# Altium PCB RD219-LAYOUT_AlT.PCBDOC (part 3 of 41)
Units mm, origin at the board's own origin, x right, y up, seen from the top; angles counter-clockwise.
Board outline 209.75 x 159.97 mm, 2 copper layers (TOP, BOTTOM), stack 0 mm thick; 398 components, 199 nets, 1469 pads, 0 vias.
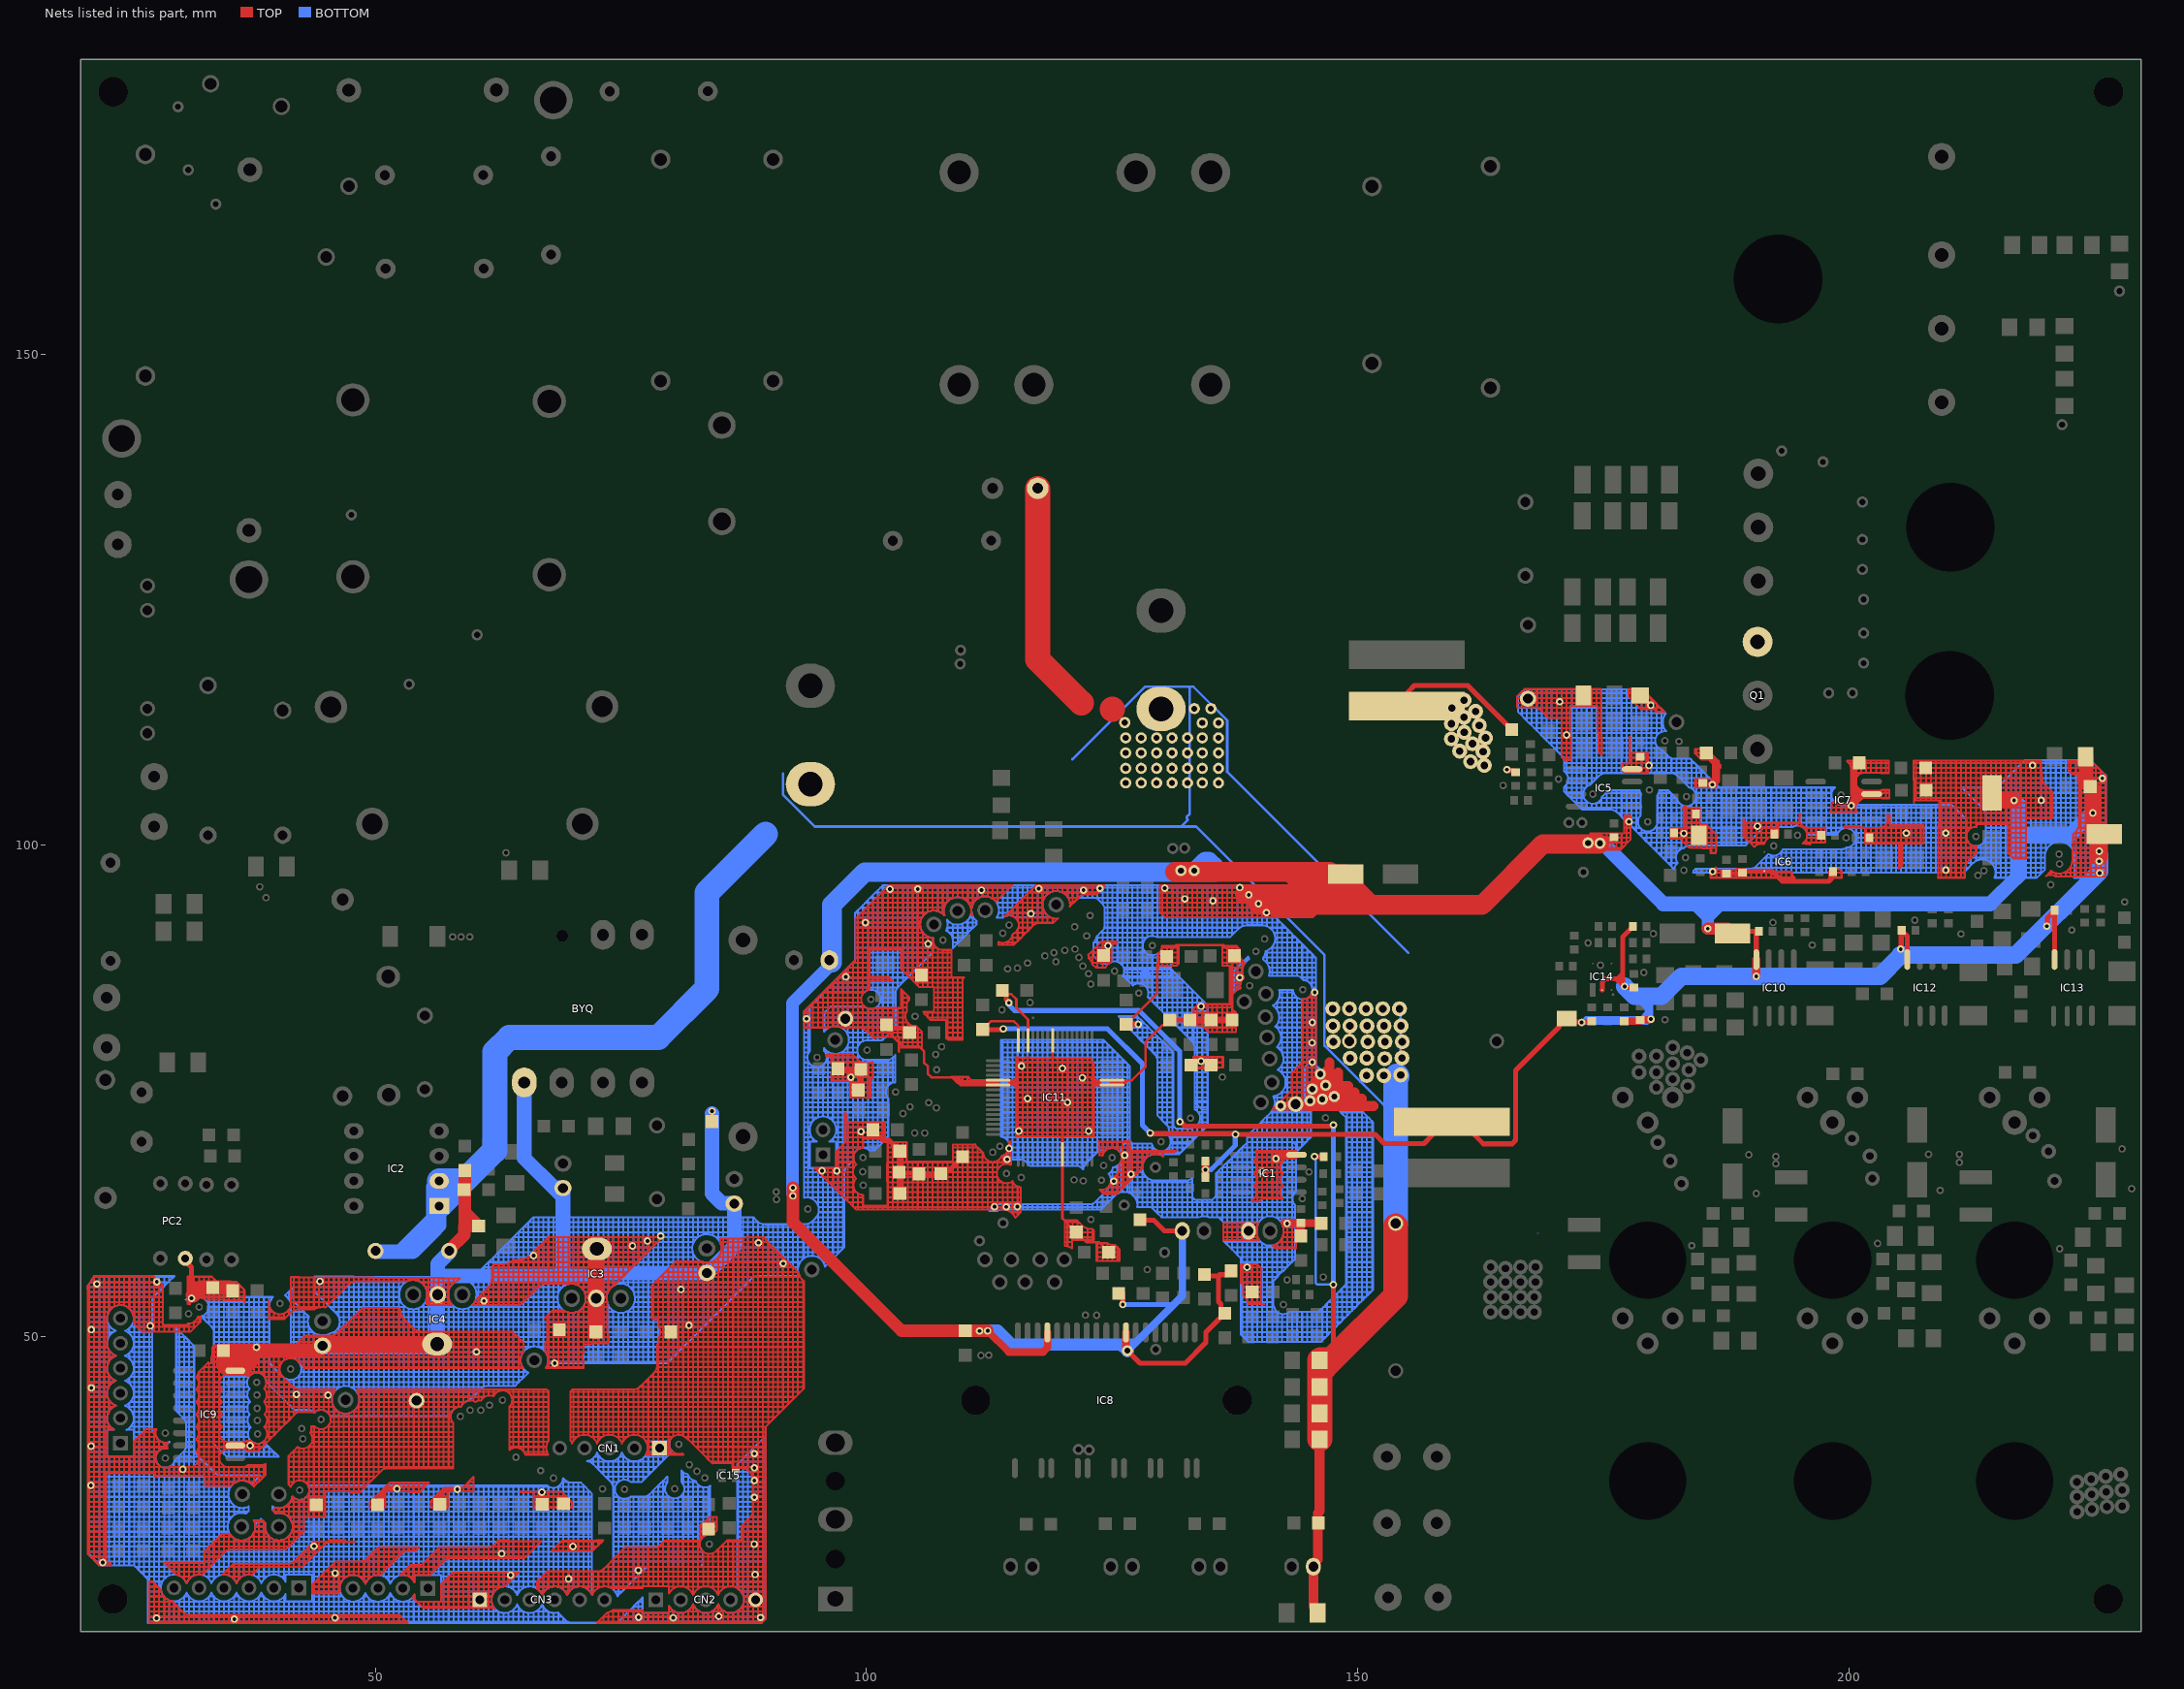
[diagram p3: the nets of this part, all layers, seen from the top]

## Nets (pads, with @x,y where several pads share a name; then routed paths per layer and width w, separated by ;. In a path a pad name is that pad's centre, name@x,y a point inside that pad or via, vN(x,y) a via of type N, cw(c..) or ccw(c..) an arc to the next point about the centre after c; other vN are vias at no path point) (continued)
GND: (continued)
  TOP w0.203: 21.355,56.068 21.397,56.068 ; 21.397,56.132 21.397,56.068 ; 21.905,56.194 21.905,56.068 ; 22.607,34.572 cw(c23.429,34.808) 22.577,34.732 ; 22.609,34.563 22.609,34.224 ; 22.611,35.058 ccw(c23.429,34.808) 22.609,35.053 ; 22.713,44.304 cw(c24.064,44.257) 22.714,44.315 ; 22.712,49.34 22.712,49.464 ; 22.712,51.874 22.712,51.496 ; 22.765,41.344 ccw(c24.064,41.717) 22.767,41.336 ; 22.765,46.424 ccw(c24.064,46.797) 22.767,46.416 ; 22.769,43.869 cw(c23.429,44.177) 22.765,43.876 ; 22.771,41.322 cw(c24.064,41.717) 22.767,41.336 ; 22.771,43.862 ccw(c24.064,44.257) 22.918,43.541 ccw(c24.064,44.257) 22.921,43.536 ; 22.771,46.402 cw(c24.064,46.797) 22.767,46.416 ; 22.921,52.598 22.921,53.02 ; 23.409,40.535 cw(c24.064,41.717) 23.046,40.828 ; 23.42,40.529 22.921,40.529 ; 25.098,36.111 24.953,36.111 ; 25.112,36.111 25.461,36.111 ; 25.416,51.874 25.416,51.496 ; 25.461,56.171 25.461,56.068 ; 26.477,56.164 26.477,56.068 ; 27.46,56.157 26.985,56.16 ; 27.661,37.773 ccw(c28.636,37.653) 27.73,37.272 ; 27.662,37.78 27.493,37.78 ; 27.663,37.79 cw(c28.636,37.653) 27.886,38.288 ; 28.192,24.22 28.001,24.411 ; 28.194,24.21 ccw(c29.525,24.445) 28.228,24.064 ; 28.4,53.673 28.4,53.528 ; 28.4,53.687 28.4,54.036 ; 28.505,23.558 ccw(c29.525,24.445) 28.507,23.556 ; 28.521,23.541 cw(c29.525,24.445) 28.509,23.554 ; 28.525,27.003 29.017,27.003 ; 28.527,27.001 29.017,26.511 ; 28.856,38.609 cw(c29.72,38.923) 28.855,38.611 ; 28.856,39.237 ccw(c29.72,38.923) 28.855,39.235 ; 28.857,38.61 ccw(c28.636,37.653) 28.855,38.611 ; 28.857,39.236 cw(c28.636,40.193) 28.855,39.235 ; 28.924,26.604 29.017,26.604 ; 29.127,36.802 cw(c28.636,37.653) 29.126,36.801 ; 29.29,23.114 cw(c29.525,24.445) 29.019,23.192 cw(c29.525,24.445) 29.017,23.193 ; 29.3,23.112 29.364,23.048 ; 29.374,36.801 29.126,36.801 ; 29.375,36.801 ccw(c29.72,37.653) 29.486,36.764 ; 29.736,25.78 cw(c29.525,24.445) 29.75,25.778 ; 30.128,27.003 30.033,27.003 ; 30.142,27.003 30.541,27.003 ; 30.178,35.857 30.033,35.857 ; 30.192,35.857 30.541,35.857 ; 30.241,25.591 ccw(c29.525,24.445) 30.033,25.698 ; 30.246,25.588 30.541,25.588 ; 30.261,25.579 cw(c29.525,24.445) 30.541,25.336 ; 30.396,22.016 30.38,22.032 ; 30.898,51.353 ccw(c31.001,52.33) 30.904,51.353 ; 30.898,53.308 cw(c31.001,52.33) 30.904,53.308 ; 30.904,53.673 30.904,53.528 ; 30.904,53.687 30.904,54.036 ; 31.045,25.332 ccw(c32.065,24.445) 30.872,25.08 ; 31.049,25.336 31.049,25.588 ; 31.049,56.133 31.049,56.068 ; 31.061,25.349 cw(c32.065,24.445) 31.344,25.588 ; 31.121,53.306 ccw(c31.001,52.33) 31.049,53.312 ; 31.127,53.296 cw(c32.071,53.026) 31.227,53.528 ; 31.778,38.285 ccw(c31.117,38.923) 31.781,38.288 ; 31.778,38.291 cw(c31.117,37.653) 31.781,38.288 ; 31.778,39.555 ccw(c31.117,40.193) 31.781,39.558 ; 31.778,39.561 cw(c31.117,38.923) 31.781,39.558 ; 31.778,40.825 ccw(c31.117,41.463) 31.781,40.828 ; 31.778,40.831 cw(c31.117,40.193) 31.781,40.828 ; 31.778,42.095 ccw(c31.117,42.733) 31.949,42.345 ; 31.778,43.365 ccw(c31.117,44.003) 31.781,43.368 ; 31.778,43.371 cw(c31.117,42.733) 31.781,43.368 ; 31.778,44.635 ccw(c31.117,45.273) 31.781,44.638 ; 31.778,44.641 cw(c31.117,44.003) 31.781,44.638 ; 31.778,45.905 ccw(c31.117,46.543) 31.781,45.908 ; 31.778,45.911 cw(c31.117,45.273) 31.781,45.908 ; 31.789,42.09 cw(c31.117,41.463) 31.953,41.844 ; 31.941,52.043 cw(c31.001,52.33) 31.928,52.004 ; 31.95,39.805 cw(c31.117,40.193) 31.781,39.558 ; 31.95,44.885 cw(c31.117,45.273) 31.781,44.638 ; 31.951,52.05 ccw(c32.071,53.026) 32.065,52.043 ; 31.953,39.812 32.065,39.812 ; 31.953,42.352 32.065,42.352 ; 31.953,44.892 32.065,44.892 ; 31.956,39.819 ccw(c31.117,40.193) 32.036,40.193 ccw(c31.117,40.193) 32.027,40.32 ; 31.956,42.359 ccw(c31.117,42.733) 32.036,42.733 ccw(c31.117,42.733) 32.027,42.86 ; 31.956,44.899 ccw(c31.117,45.273) 32.036,45.273 ccw(c31.117,45.273) 32.027,45.4 ; 32.024,46.399 cw(c31.117,46.543) 31.781,45.908 ; 32.025,46.405 32.036,46.416 ; 32.065,56.127 32.065,56.068 ; 32.1,51.42 32.065,51.386 ; 32.21,51.52 32.21,52.004 ; 32.225,52.055 cw(c32.071,53.026) 32.21,52.053 ; 32.346,25.767 ccw(c32.065,24.445) 32.065,25.797 ; 32.355,25.765 32.573,25.983 ; 32.631,28.183 32.631,28.128 ; 32.716,53.767 ccw(c32.071,53.026) 32.573,53.87 ; 32.72,53.764 33.081,53.764 ; 33.02,47.4 32.943,47.323 ; 33.081,28.622 33.081,28.128 ; 33.317,47.846 33.317,47.432 ; 33.589,49.087 33.589,48.956 ; 34.21,37.279 ccw(c35.05,37.653) 34.213,37.272 ; 34.21,41.837 ccw(c35.05,41.463) 34.139,41.336 ; 34.21,44.377 ccw(c35.05,44.003) 34.139,43.876 ; 34.213,41.844 34.097,41.844 ; 34.213,44.384 34.097,44.384 ; 34.217,37.265 cw(c35.05,37.653) 34.213,37.272 ; 34.217,41.851 cw(c35.05,41.463) 34.388,42.101 ; 34.217,44.391 cw(c35.05,44.003) 34.388,44.641 ; 34.377,42.106 cw(c35.05,42.733) 34.213,42.352 ; 34.377,44.646 cw(c35.05,45.273) 34.213,44.892 ; 34.388,40.825 cw(c35.05,41.463) 34.385,40.828 ; 34.388,40.831 ccw(c35.05,40.193) 34.385,40.828 ; 34.388,43.365 cw(c35.05,44.003) 34.385,43.368 ; 34.388,43.371 ccw(c35.05,42.733) 34.385,43.368 ; 34.436,25.786 34.605,25.955 ; 34.44,25.787 cw(c34.605,24.445) 34.605,25.797 ; 34.604,36.849 cw(c35.05,37.653) 34.213,37.272 ; 34.604,38.457 ccw(c35.05,37.653) 34.385,38.288 ; 34.604,39.389 cw(c35.05,40.193) 34.213,39.812 ; 34.714,53.727 35.113,53.727 ; 34.714,53.764 34.605,53.764 ; 34.718,28.128 34.605,28.128 ; 35.182,29.946 ccw(c36.383,30.668) 35.186,29.939 ; 35.353,34.826 35.113,34.826 ; 35.359,34.833 cw(c36.463,33.97) 35.62,35.089 cw(c36.463,33.97) 35.621,35.09 ; 35.871,35.24 cw(c36.463,33.97) 36.124,35.33 cw(c36.463,33.97) 36.129,35.331 ; 36.116,29.292 cw(c36.383,30.668) 35.621,29.492 ; 36.125,25.332 ccw(c37.145,24.445) 35.952,25.08 ; 36.129,25.336 36.129,25.588 ; 36.129,29.29 36.129,29.144 ; 36.14,29.288 ccw(c36.383,30.668) 36.637,29.29 ; 36.141,25.349 cw(c37.145,24.445) 36.424,25.588 ; 36.626,29.288 ccw(c36.383,30.668) 36.637,29.29 ; 36.65,29.292 cw(c36.383,30.668) 36.637,29.29 ; 36.704,53.727 36.637,53.727 ; 36.732,53.419 36.732,54.036 ; 36.947,39.422 cw(c36.447,40.193) 36.68,39.304 ; 36.947,46.044 ccw(c36.447,45.273) 36.946,46.045 ; 36.948,39.423 37.145,39.423 ; 37.012,36.929 cw(c36.447,37.653) 37.007,36.924 ; 37.012,38.377 ccw(c36.447,37.653) 37.007,38.382 ; 37.126,29.479 cw(c36.383,30.668) 36.637,29.29 ; 37.145,29.492 37.145,29.144 ; 37.146,29.493 ccw(c36.383,30.668) 37.349,29.652 ; 37.223,46.042 cw(c37.93,45.359) 37.226,46.045 ; 37.317,39.427 ccw(c38.024,40.11) 37.321,39.423 ; 37.426,25.767 ccw(c37.145,24.445) 37.145,25.797 ; 37.435,25.765 37.653,25.983 ; 37.615,31.336 38.161,31.336 ; 37.621,31.326 cw(c36.383,30.668) 37.689,31.176 ; 37.639,34.732 38.669,35.762 ; 37.638,34.733 ccw(c36.463,33.97) 37.145,35.194 ; 37.653,30.076 ccw(c36.383,30.668) 37.689,30.16 ; 37.653,34.746 37.653,35.24 ; 38.147,35.24 37.653,35.24 ; 38.161,35.254 38.161,35.748 ; 38.655,35.748 38.161,35.748 ; 38.668,39.368 cw(c38.024,40.11) 38.586,39.304 ; 38.674,43.393 ccw(c37.967,44.076) 38.929,43.876 ; 38.68,43.395 cw(c37.973,42.712) 38.705,43.368 ; 38.694,44.741 ccw(c37.93,45.359) 38.795,44.892 ; 38.697,44.733 cw(c37.967,44.076) 38.9,44.384 ; 38.706,40.817 cw(c38.024,40.11) 38.983,40.32 ; 38.714,40.814 ccw(c37.995,41.485) 38.726,40.828 ; 38.747,42.107 ccw(c37.973,42.712) 38.887,42.352 ; 38.759,42.103 cw(c37.995,41.485) 38.91,41.844 ; 38.829,37.058 38.829,36.764 ; 38.833,31.007 ccw(c40.193,30.668) 38.831,30.999 ; 39.168,29.712 cw(c40.193,30.668) 38.887,30.16 ; 39.177,29.702 39.177,29.652 ; 39.185,29.694 ccw(c40.193,30.668) 39.227,29.652 ; 39.195,53.386 ccw(c40.296,53.386) 39.207,53.224 ; 39.195,53.419 39.195,53.727 ; 39.685,32.432 39.685,32.206 ; 39.854,32.028 cw(c40.193,30.668) 39.862,32.03 ; 39.854,32.61 ccw(c40.193,33.97) 39.862,32.608 ; 40.181,52.291 cw(c40.296,53.386) 39.685,52.47 ; 40.193,52.29 40.193,52.004 ; 40.2,52.289 ccw(c40.296,53.386) 40.701,52.362 ; 40.624,45.908 40.193,45.908 ; 40.695,31.977 ccw(c40.193,30.668) 40.193,32.07 ; 40.701,31.974 40.701,32.192 ; 40.701,45.831 40.701,45.4 ; 40.718,31.968 cw(c40.193,30.668) 41.159,31.684 ; 40.785,32.7 cw(c40.193,33.97) 40.701,32.664 ; 41.176,34.969 41.176,35.24 ; 41.184,34.961 cw(c40.193,33.97) 41.209,34.936 ; 41.209,37.893 41.209,37.78 ; 41.355,52.411 41.209,52.264 ; 41.378,34.709 cw(c42.307,34.389) 41.38,34.715 ; 41.382,34.713 ccw(c40.193,33.97) 41.38,34.715 ; 41.573,33.727 cw(c40.193,33.97) 41.369,33.208 ; 41.574,44.959 41.209,45.323 ; 41.577,33.732 ccw(c42.307,34.389) 41.717,33.604 ; 41.716,35.174 ccw(c42.307,34.389) 41.38,34.715 ; 42.09,38.785 ccw(c42.625,39.609) 42.097,38.781 ; 42.211,29.652 41.717,29.652 ; 42.225,27.606 42.225,27.112 ; 42.278,49.511 42.739,49.972 ; 42.592,26.604 42.225,26.604 ; 42.719,30.16 42.225,30.16 ; 42.733,26.745 42.733,27.112 ; 42.733,28.114 42.733,27.62 ; 42.733,49.966 42.733,49.464 ; 43.1,27.112 42.733,27.112 ; 43.241,27.253 43.241,27.62 ; 43.241,28.622 43.241,28.128 ; 43.389,40.227 cw(c42.625,39.609) 43.587,39.812 ; 43.396,40.227 ccw(c42.513,40.658) 43.435,40.32 ; 43.466,40.896 cw(c42.513,40.658) 43.467,40.891 ; 43.608,27.62 43.241,27.62 ; 43.749,27.761 43.749,28.128 ; 43.749,29.13 pad.@43.749,28.636 ; 43.788,40.895 ccw(c44.482,41.59) 43.792,40.891 ; 43.84,52.806 cw(c44.575,51.583) 43.842,52.808 ; 43.857,42.348 43.749,42.348 ; 43.862,42.352 43.749,42.352 ; 43.864,42.354 cw(c44.482,41.59) 44.257,42.546 ; 44.116,28.128 43.749,28.128 ; 44.245,40.637 cw(c44.482,41.59) 43.862,40.828 ; 44.257,28.269 44.257,28.636 ; 44.257,40.634 44.257,40.32 ; 44.261,40.633 ccw(c44.482,41.59) 44.765,40.649 ; 44.624,28.636 44.257,28.636 ; 44.91,31.779 44.91,31.684 ; 44.91,31.793 44.91,32.192 ; 44.949,52.988 ccw(c44.702,51.583) 44.765,53.009 ; 44.956,52.987 45.273,53.304 ; 44.989,53.02 44.765,53.02 ; 45.101,42.354 ccw(c44.482,41.59) 44.77,42.53 ccw(c44.482,41.59) 44.765,42.531 ; 45.103,42.352 45.273,42.352 ; 45.114,42.343 cw(c44.482,41.59) 45.273,42.173 ; 45.267,40.999 cw(c44.482,41.59) 45.103,40.828 ; 45.273,41.007 45.273,40.828 ; 45.277,41.012 ccw(c44.482,41.59) 45.432,41.336 ; 45.497,53.528 45.273,53.528 ; 45.954,44.532 ccw(c46.979,43.576) 45.949,44.527 ; 46.278,42.363 cw(c46.979,43.576) 45.781,42.849 ; 46.289,42.357 46.289,42.352 ; 46.293,50.501 46.78,50.988 ; 46.297,42.352 46.289,42.352 ; 46.3,42.351 ccw(c46.979,43.576) 46.797,42.187 ; 46.79,25.369 ccw(c47.729,24.397) 46.562,25.08 ; 46.797,25.376 46.797,25.588 ; 46.797,51.005 46.797,50.988 ; 46.807,25.386 cw(c47.729,24.397) 47.09,25.588 ; 47.214,55.245 47.021,55.052 ; 47.8,25.747 cw(c47.729,24.397) 47.813,25.746 ; 47.823,25.745 ccw(c47.729,24.397) 47.813,25.746 ; 47.892,29.111 46.797,29.111 ; 47.926,29.144 46.797,29.144 ; 47.944,29.162 46.942,29.162 46.942,29.289 46.797,29.289 ; 48.153,44.343 48.153,44.384 ; 48.155,44.34 cw(c46.979,43.576) 48.321,43.981 ; 48.18,42.855 ccw(c46.979,43.576) 48.184,42.86 ; 48.193,42.876 cw(c46.979,43.576) 48.184,42.86 ; 48.363,25.59 ccw(c47.729,24.397) 48.321,25.612 ; 48.368,25.588 48.829,25.588 ; 48.384,25.579 cw(c47.729,24.397) 48.829,25.182 ; 49.33,25.369 ccw(c50.269,24.397) 49.102,25.08 ; 49.337,25.376 49.337,25.588 ; 49.337,27.606 49.337,27.112 ; 49.347,25.386 cw(c50.269,24.397) 49.63,25.588 ; R74.1@49.845,33.524 R74.1@49.845,33.208 ; 50.353,34.032 50.353,33.716 ; 50.48,25.732 ccw(c50.269,24.397) 50.353,25.746 ; 50.482,25.732 50.847,26.096 ; 50.516,36.256 50.353,36.256 ; 52.531,25.72 52.893,26.082 ; 52.551,25.724 cw(c52.809,24.397) 52.893,25.746 ; 52.936,51.799 53.239,51.496 ; 53.248,55.642 52.893,55.642 ; 53.259,55.647 cw(c53.862,54.354) 53.401,55.704 ; 53.51,34.206 53.909,34.206 ; 53.51,34.224 53.909,34.224 ; 53.51,34.282 53.401,34.282 ; 53.813,50.922 53.747,50.988 ; 53.813,23.493 ccw(c52.809,24.397) 53.867,23.556 ; 53.815,23.465 53.997,23.283 ; 53.909,23.371 53.909,23.556 ; 53.991,23.742 cw(c52.809,24.397) 53.909,23.612 ; 53.997,23.753 53.997,23.556 ; 54.002,25.032 ccw(c52.809,24.397) 53.997,25.041 ; 54.417,22.863 54.417,23.045 ; 55.241,53.857 ccw(c53.862,54.227) 55.243,53.865 ; 57.835,53.235 cw(c58.862,54.227) 57.618,53.528 ; 57.842,53.229 57.465,53.229 ; 57.925,36.604 57.465,36.604 ; 57.926,41.238 cw(c58.656,41.895) 57.848,41.336 ; 57.928,36.606 57.928,36.764 ; 57.928,41.236 57.928,40.828 ; 57.964,55.463 ccw(c58.862,54.354) 57.618,55.052 ; 57.973,55.47 57.973,55.56 ; 57.974,42.602 cw(c58.656,41.895) 58.471,42.86 ; 57.983,55.478 cw(c58.862,54.354) 58.1,55.56 ; 58.351,55.686 ccw(c58.862,54.354) 58.344,55.683 ; 58.723,42.866 cw(c59.646,42.53) 58.989,43.261 ; 58.725,42.875 ccw(c58.656,41.895) 58.486,42.863 ccw(c58.656,41.895) 58.481,42.862 ; 59.87,34.216 60.005,34.216 ; 59.87,34.224 60.005,34.224 ; 59.87,34.276 59.497,34.276 ; 59.882,53.229 60.005,53.229 ; 59.889,53.235 ccw(c58.862,54.227) 60.005,53.372 ; 59.998,43.447 ccw(c59.646,42.53) 59.497,43.501 ; 60.005,43.445 60.005,43.876 ; 60.014,43.441 cw(c59.646,42.53) 60.195,43.345 ; 60.194,53.715 cw(c58.862,54.227) 60.192,53.708 ; 60.206,43.354 cw(c60.741,42.53) 60.513,43.486 ; 60.513,54.03 60.513,53.528 ; 60.772,43.514 cw(c61.632,43.038) 61.021,43.808 ; 60.776,43.512 ccw(c60.741,42.53) 60.52,43.487 ccw(c60.741,42.53) 60.513,43.486 ; 61.021,54.538 61.021,54.036 ; 61.468,54.984 61.027,54.544 ; 62.037,57.332 62.037,57.084 ; 62.047,43.929 ccw(c61.632,43.038) 62.042,43.931 ; 62.16,22.354 cw(c63.18,23.241) 62.145,22.372 ; 63.18,24.593 ccw(c63.18,23.241) 63.053,24.587 ; 63.186,24.593 63.561,24.967 ; 63.61,29.212 64.069,29.212 ; 63.61,29.283 63.561,29.283 ; 63.672,38.481 cw(c64.317,37.739) 63.675,38.483 ; 63.675,42.887 63.675,42.86 ; 63.676,42.889 ccw(c62.946,43.546) 63.913,43.368 ; 64.017,57.787 64.069,57.787 ; 64.731,34.211 pad.@66.609,34.211 ; 64.738,34.204 66.113,34.204 66.113,33.716 ; 64.941,49.525 64.577,49.889 ; 64.941,53.391 64.779,53.229 64.577,53.229 ; 64.943,53.392 65.079,53.528 ; 64.983,49.464 64.577,49.464 ; 65.028,46.827 cw(c66.19,47.61) 65.02,46.838 ; 65.091,48.48 65.091,48.956 ; 65.091,49.396 65.091,48.956 ; 65.262,38.01 ccw(c64.317,37.739) 65.132,38.288 ; 65.263,38.004 65.593,38.004 ; 65.325,27.62 65.085,27.62 ; 65.583,58.118 cw(c64.827,59.239) 65.555,58.1 ; 65.738,29.213 66.609,29.213 ; pad.@65.783,58.283 cw(c64.827,59.239) 65.602,58.132 ; pad.@65.784,58.284 cw(c64.827,59.239) 65.602,58.132 ; pad.@65.799,58.3 cw(c64.827,59.239) 65.784,58.285 pad.@66.107,58.608 ; pad.@66.101,58.602 pad.@66.101,58.1 ; 66.113,29.212 66.101,29.212 ; 66.341,28.636 66.101,28.636 ; 66.436,24.387 cw(c65.72,23.241) 66.449,24.379 ; 66.475,28.77 66.101,28.396 ; 66.475,28.771 66.609,28.904 ; 66.541,54.991 66.101,54.55 ; 66.609,59.11 66.609,58.608 ; 66.785,24.073 ccw(c65.72,23.241) 66.609,24.259 ; 66.792,24.064 67.117,24.064 ; 66.799,24.054 cw(c65.72,23.241) 66.99,23.704 cw(c68.26,23.241) 67.114,23.957 cw(c68.26,23.241) 67.117,23.962 ; 67.117,59.618 67.117,59.116 ; 67.249,51.876 67.323,51.95 ; 67.294,48.474 67.294,48.956 ; 67.294,48.473 cw(c66.19,47.61) 67.314,48.448 ; 67.36,46.838 67.625,46.838 ; 67.365,46.847 ccw(c66.19,47.61) 67.412,46.924 ; 67.469,38.296 ccw(c68.768,38.669) 67.471,38.288 ; 67.475,38.274 cw(c68.768,38.669) 67.471,38.288 ; 67.586,38.014 cw(c68.768,38.669) 67.471,38.288 ; 67.591,38.004 67.117,38.004 ; 67.625,60.126 67.625,59.624 ; 67.661,39.444 ccw(c68.768,38.669) 67.625,39.39 ; 67.666,39.452 67.666,39.812 ; 68.133,28.368 68.133,28.222 ; 69.152,52.691 ccw(c69.991,53.846) 69.161,52.684 ; 69.325,24.073 ccw(c68.26,23.241) 69.149,24.259 ; 69.332,24.064 69.657,24.064 ; 69.339,24.054 cw(c68.26,23.241) 69.53,23.704 cw(c70.8,23.241) 69.654,23.957 cw(c70.8,23.241) 69.657,23.962 ; 69.792,55.386 cw(c69.991,53.973) 69.806,55.388 ; 69.87,39.452 69.87,39.812 ; 69.875,39.444 cw(c68.768,38.669) 69.961,39.304 ; 70.016,29.241 70.165,29.241 ; 70.404,29.244 69.657,29.244 ; 70.908,55.066 cw(c69.991,53.973) 70.924,55.052 ; 70.927,55.05 ccw(c69.991,53.973) 70.924,55.052 ; 71.167,40.013 cw(c71.308,38.669) 71.181,40.015 ; 71.19,40.015 ccw(c71.308,38.669) 71.181,40.015 ; 71.198,47.484 cw(c72.451,47.991) 71.181,47.528 ; 71.198,48.497 ccw(c72.451,47.991) 71.181,48.453 ; 71.199,47.481 71.199,47.432 ; 71.199,48.501 71.199,48.956 ; 71.865,24.073 ccw(c70.8,23.241) 71.689,24.259 ; 71.872,24.064 72.197,24.064 ; 71.879,24.054 cw(c70.8,23.241) 72.07,23.704 cw(c73.34,23.241) 72.194,23.957 ; 71.941,49.242 71.689,49.242 ; 71.945,49.244 cw(c72.451,47.991) 72.193,49.318 cw(c72.451,47.991) 72.197,49.318 ; 72.197,23.962 72.197,24.064 ; 72.206,23.977 cw(c73.34,23.241) 72.268,24.064 ; 72.519,29.241 72.197,29.241 ; 72.519,29.289 72.705,29.289 ; 73.642,53.381 cw(c74.991,53.846) 73.639,53.387 ; 73.707,40.013 cw(c73.848,38.669) 73.721,40.015 ; 73.721,26.844 73.721,26.604 ; 73.73,40.015 ccw(c73.848,38.669) 73.721,40.015 ; 73.738,49.974 cw(c74.991,50.48) 73.721,50.018 ; 73.739,49.972 73.721,49.972 ; 73.739,49.97 73.739,49.464 ; 74.036,24.4 ccw(c73.34,23.241) 74.029,24.404 ; 74.209,22.206 cw(c73.34,23.241) 74.203,22.2 ; 74.229,27.352 74.229,27.112 ; 74.365,55.255 ccw(c74.991,53.972) 74.359,55.252 ; 75.652,39.803 cw(c76.388,38.669) 75.667,39.812 ; 75.672,39.815 ccw(c76.388,38.669) 75.667,39.812 ; 75.844,56.737 75.753,56.646 ; 75.846,56.739 76.191,57.084 ; 76.997,44.959 77.277,45.239 ; 77.565,38.004 77.785,38.004 ; 77.57,38.014 ccw(c76.388,38.669) 77.613,38.098 ccw(c76.388,38.669) 77.685,38.288 ; 77.732,38.81 cw(c76.388,38.669) 77.734,38.796 ; 77.734,38.787 ccw(c76.388,38.669) 77.734,38.796 ; 78.36,46.322 78.293,46.255 ; 78.683,49.21 78.683,48.956 ; 78.683,49.228 78.801,49.228 ; 78.801,55.871 78.801,55.56 ; 78.829,49.804 ccw(c77.658,50.48) 78.833,49.813 ; 78.829,51.156 cw(c77.658,50.48) 78.833,51.147 ; pad.@79.051,59.944 78.801,59.694 ; pad.@79.053,59.946 79.211,60.103 79.239,60.132 pad.@78.801,60.132 ; 79.309,29.096 79.309,28.636 ; 79.894,22.606 ccw(c81.087,23.241) 79.899,22.597 ; 79.899,23.885 79.899,24.064 ; 79.905,23.896 cw(c81.087,23.241) 80.015,24.064 ; 79.946,39.305 cw(c80.895,39.051) 80.274,39.812 ; 80.263,39.803 cw(c80.895,39.051) 80.274,39.812 ; 80.276,39.814 ccw(c80.895,39.051) 80.274,39.812 ; 80.562,29.256 81.341,29.256 ; 80.928,29.242 80.833,29.242 ; 81.231,38.127 cw(c80.895,39.051) 80.325,38.25 ; 81.233,38.128 81.357,38.004 80.325,38.004 ; 81.658,39.669 ccw(c80.895,39.051) 81.656,39.672 ; 82.152,24.073 ccw(c81.087,23.241) 81.849,24.357 ; 82.159,24.064 82.357,24.064 ; 82.166,24.054 cw(c81.087,23.241) 82.357,23.704 82.357,24.064 ; 82.233,22.525 cw(c81.087,23.241) 81.849,22.125 ; 82.243,22.54 82.357,22.54 ; 82.246,22.545 ccw(c81.087,23.241) 82.357,22.778 ; 82.365,23.725 cw(c83.627,23.241) 82.555,24.064 ; 83.065,30.897 83.065,30.668 ; 83.226,57.64 ccw(c83.691,58.989) 83.232,57.637 ; C110.2@84.295,29.83 ccw(c84.008,28.89) C110.2@83.881,29.864 ; C110.2@84.298,29.829 84.416,29.948 84.775,30.307 84.775,30.668 ; 84.318,37.104 84.149,37.272 ; 84.323,37.152 84.389,37.152 ; C110.2@84.389,29.92 C110.2@84.389,30.16 ; 84.629,30.16 C110.2@84.389,30.16 ; 84.692,24.073 ccw(c83.627,23.241) 84.389,24.357 ; 84.699,24.064 84.897,24.064 ; 84.706,24.054 cw(c83.627,23.241) 84.897,23.704 84.897,24.064 ; 84.773,22.525 cw(c83.627,23.241) 84.389,22.125 ; 84.783,22.54 84.897,22.54 ; 84.786,22.545 ccw(c83.627,23.241) 84.897,22.778 ; 84.823,28.341 cw(c84.008,28.89) 84.628,28.128 ; 84.905,23.725 cw(c86.167,23.241) 85.095,24.064 ; 84.927,58.091 ccw(c83.818,58.989) 84.934,58.1 ; 84.942,58.11 cw(c83.818,58.989) 84.934,58.1 ; 85.106,59.603 85.106,59.624 ; 85.111,59.592 cw(c83.818,58.989) 85.239,59.116 ; 85.189,58.596 cw(c83.818,58.989) 84.934,58.1 ; 85.193,58.608 85.405,58.608 ; 85.196,58.62 ccw(c83.818,58.989) 85.245,58.989 ccw(c83.818,58.989) 85.239,59.116 ; 85.392,22.134 cw(c86.167,23.241) 85.011,22.54 ; 85.405,22.125 85.405,22.032 ; 85.411,22.12 ccw(c86.167,23.241) 85.563,22.032 ; 87.232,24.073 ccw(c86.167,23.241) 86.929,24.357 ; 87.239,24.064 87.437,24.064 ; 87.246,24.054 cw(c86.167,23.241) 87.437,23.704 ; 87.313,22.525 cw(c86.167,23.241) 86.929,22.125 ; 87.323,22.54 87.437,22.54 ; 87.326,22.545 ccw(c86.167,23.241) 87.437,22.778 ; 87.782,60.132 87.945,60.132 ; 89.596,60.132 89.469,60.132 ; 93.045,56.57 93.038,56.576 ; 93.046,56.563 ccw(c94.422,56.83) 93.246,56.068 ; 93.659,55.655 cw(c94.422,56.83) 93.533,55.746 ; 93.66,49.972 93.533,49.972 ; 93.66,55.654 93.66,55.56 ; 95.894,78.736 96.073,78.736 ; 95.899,78.722 cw(c94.965,78.418) 95.941,78.529 ; 95.942,78.521 ccw(c94.965,78.418) 95.941,78.529 ; 96.436,76.767 96.436,76.388 ; 96.436,77.787 96.436,77.912 ; 96.437,76.771 ccw(c95.184,77.277) R144.1@96.481,76.896 ; 96.437,77.783 cw(c95.184,77.277) R144.1@96.53,77.404 ; 97.818,72.777 97.818,72.324 ; 98.721,65.705 cw(c99.661,65.418) 98.726,65.72 ; 98.727,65.721 ccw(c99.661,65.418) 98.726,65.72 ; 98.931,66.075 ccw(c99.661,65.418) 98.726,65.72 ; 98.941,66.077 cw(c99.611,66.795) 98.809,66.228 ; 98.953,67.526 ccw(c99.611,66.795) 98.737,67.244 ; 98.96,67.529 cw(c99.642,68.236) 98.791,67.745 cw(c99.642,68.236) 98.787,67.752 ; 99.642,69.219 ccw(c99.642,68.236) 99.629,69.218 ; 99.644,64.435 cw(c99.661,65.418) 99.629,64.436 ; 99.647,64.435 99.647,64.196 ; 99.647,69.219 99.647,69.276 ; 99.923,83.501 cw(c100.444,84.334) 99.629,83.784 ; 100.084,81.043 100.137,80.99 ; 100.307,85.307 ccw(c100.444,84.334) 100.137,85.267 ; 100.313,85.308 100.313,85.532 ; 100.486,71.834 100.137,71.834 ; 100.5,71.834 100.645,71.834 ; 100.643,77.95 cw(c100.051,79.165) 100.557,77.912 ; 100.645,77.951 100.645,77.912 ; 100.652,77.955 100.652,77.912 ; 100.859,83.443 cw(c100.444,84.334) 100.855,83.441 ; 102.074,65.829 102.074,66.228 ; 102.074,67.643 102.074,67.244 ; 102.151,65.829 102.151,65.72 ; 102.151,67.643 102.151,67.752 ; 103.294,79.012 103.294,79.436 ; 103.33,78.975 103.33,79.418 103.693,79.418 ; 104.085,83.091 ccw(c104.936,82.599) 104.084,83.089 ; 104.346,84.266 104.346,84.516 ; 104.393,86.548 104.709,86.548 ; 104.463,86.479 104.709,86.232 ; 104.462,86.479 104.201,86.74 ; 105.055,81.624 cw(c104.936,82.599) 105.048,81.623 ; 105.467,92.137 cw(c106.858,91.966) 105.631,92.644 ; 105.616,79.708 105.616,79.944 ; 105.631,79.708 105.631,79.436 ; 105.724,91.143 cw(c106.858,91.966) 105.498,91.627 ; 105.803,83.061 106.233,83.061 ; 105.803,83.061 cw(c104.936,82.599) 105.836,82.992 ; 105.889,82.837 ccw(c104.936,82.599) 105.887,82.844 ; 106.222,90.718 cw(c106.858,91.966) 105.741,91.12 ; 106.233,90.712 106.233,90.612 ; 106.244,90.707 ccw(c106.858,91.966) 106.498,90.612 ; 106.298,67.846 106.741,67.846 ; 106.496,90.613 ccw(c106.858,91.966) 106.498,90.612 ; 106.519,90.606 cw(c106.858,91.966) 106.498,90.612 ; 106.585,67.814 106.233,67.814 ; 106.785,90.567 cw(c106.858,91.966) 106.741,90.57 ; 106.798,90.571 ccw(c107.777,90.362) 106.81,90.104 106.741,90.104 ; 106.81,90.103 ccw(c107.777,90.362) 107.132,89.596 ; 107.932,92.867 ccw(c106.858,91.966) 107.759,93.04 ccw(c106.858,91.966) 107.757,93.042 ; 107.933,92.869 cw(c109.258,93.325) 107.882,93.058 cw(c109.258,93.325) 107.867,93.152 ; 108.115,80.365 cw(c107.639,79.506) 108.12,80.363 ; 108.297,80.236 ccw(c107.639,79.506) 108.265,80.263 ; 108.298,80.234 108.773,80.234 ; 108.598,76.445 108.773,76.445 ; 108.653,76.395 108.66,76.388 ; 108.664,89.056 108.664,88.58 ; 108.664,89.07 108.664,89.088 ; 108.773,76.275 108.773,76.388 ; 110.378,94.168 ccw(c109.258,93.325) 110.297,94.266 ; 110.618,93.664 ccw(c109.258,93.325) 110.378,94.168 110.805,94.168 ; 110.619,93.66 110.697,93.66 ; 110.624,93.01 ccw(c109.258,93.325) 110.626,93.02 ; 110.624,93.64 cw(c109.258,93.325) 110.626,93.02 ; 110.785,92.858 cw(c112.075,93.406) 110.783,92.863 ; 110.805,93.998 ccw(c112.075,93.406) 110.697,93.66 ; 111.041,69.548 110.805,69.548 ; 111.312,94.581 ccw(c112.075,93.406) 110.899,94.168 ; 111.313,94.582 111.313,94.676 ; 111.332,94.595 cw(c112.075,93.406) 111.482,94.676 ; 111.808,94.782 cw(c112.075,93.406) 111.821,94.784 ; 111.832,94.786 ccw(c112.075,93.406) 111.821,94.784 ; 111.872,68.695 ccw(c112.851,68.781) 112.018,68.26 ; 111.872,68.703 111.821,68.754 ; 112.103,75.835 110.805,75.835 ; 112.103,75.877 111.222,75.877 ; 112.105,75.835 cw(c112.287,75.106) 112.172,75.849 cw(c112.287,75.106) 112.235,75.856 cw(c112.287,76.606) 112.105,75.877 ; 112.318,94.786 ccw(c112.075,93.406) 111.821,94.784 ; 112.329,94.784 112.329,95.184 ; 112.342,94.782 cw(c112.075,93.406) 112.668,94.676 ; 113.179,94.269 ccw(c112.075,93.406) 113.172,94.278 ; 113.269,66.73 ccw(c114.245,66.61) 113.339,66.228 ; 113.27,66.736 112.837,66.736 ; 113.272,66.747 cw(c114.245,66.61) 113.345,67.005 ; 113.448,90.165 ccw(c113.863,91.056) 113.454,90.163 ; 113.492,67.242 ccw(c114.245,66.61) 113.347,67.01 ccw(c114.245,66.61) 113.345,67.005 ; 113.494,67.244 113.345,67.244 ; 113.503,67.255 cw(c114.245,66.61) 113.853,67.511 ; 113.762,68.413 cw(c112.851,68.781) 113.684,68.26 ; 113.764,68.415 ccw(c113.576,69.379) 113.853,68.436 ; 114.06,92.766 cw(c114.506,91.891) 114.353,92.861 ; 114.108,92.805 114.455,93.152 ; 114.361,92.862 114.361,93.058 ; 114.37,92.864 cw(c114.506,91.891) 114.869,92.804 ; 114.436,69.856 cw(c113.576,69.379) 114.472,69.784 ; 114.487,69.854 ccw(c114.487,70.606) 114.719,69.891 ; 114.587,95.692 114.361,95.692 ; 114.691,67.486 ccw(c114.245,66.61) 114.685,67.488 ; 114.722,69.888 ccw(c115.437,69.656) 114.696,69.784 ; 114.84,65.834 ccw(c115.751,66.202) 114.842,65.83 ; 114.842,90.967 ccw(c114.506,91.891) 114.869,90.977 ; 114.842,90.97 cw(c113.863,91.056) 114.74,90.612 ; 114.85,65.836 cw(c114.245,66.61) 114.842,65.83 ; 114.856,62.532 cw(c113.9,61.576) 114.869,62.518 ; 114.858,92.808 cw(c114.506,91.891) 114.869,92.804 ; 114.863,75.757 cw(c114.487,75.106) 114.869,75.753 ; 114.874,75.75 ccw(c114.487,75.106) 114.869,75.753 ; 114.874,92.802 ccw(c114.506,91.891) 114.869,92.804 ; 115.144,62.104 ccw(c113.9,61.576) 115.144,62.106 ; 115.168,78.424 cw(c114.487,78.106) 115.17,78.42 ; 115.192,70.367 cw(c115.437,69.656) 115.377,70.405 ; pad.@115.193,70.863 cw(c114.487,70.606) pad.@115.213,70.8 ; 115.196,74.356 115.377,74.356 ; pad.@115.198,70.861 ccw(c114.487,71.106) 115.239,71.106 ccw(c114.487,71.106) 115.211,71.308 ; 115.198,71.351 cw(c114.487,71.106) 115.211,71.308 ; 115.198,71.361 ccw(c114.487,71.606) 115.239,71.606 ccw(c114.487,71.606) 115.209,71.816 ; 115.198,71.851 cw(c114.487,71.606) 115.209,71.816 ; 115.198,71.861 ccw(c114.487,72.106) 115.239,72.106 ccw(c114.487,72.106) 115.206,72.324 ; 115.198,72.351 cw(c114.487,72.106) 115.206,72.324 ; 115.198,72.361 ccw(c114.487,72.606) 115.239,72.606 ccw(c114.487,72.606) 115.204,72.832 ; 115.198,72.851 cw(c114.487,72.606) 115.204,72.832 ; 115.198,72.861 ccw(c114.487,73.106) 115.239,73.106 ccw(c114.487,73.106) 115.201,73.34 ; 115.198,73.351 cw(c114.487,73.106) 115.201,73.34 ; 115.198,73.361 ccw(c114.487,73.606) 115.239,73.606 ccw(c114.487,73.606) 115.199,73.848 ; 115.198,73.851 cw(c114.487,73.606) 115.199,73.848 ; 115.198,73.861 ccw(c114.487,74.106) 115.239,74.106 ccw(c114.487,74.106) 115.198,74.351 ; 115.198,74.361 ccw(c114.487,74.606) 115.239,74.606 ccw(c114.487,74.606) 115.198,74.851 ; 115.198,74.861 ccw(c114.487,75.106) 115.199,74.864 ; 115.198,76.851 cw(c114.487,76.606) 115.239,76.606 cw(c114.487,76.606) 115.206,76.388 ; 115.198,76.861 ccw(c114.487,77.106) 115.209,76.896 ; 115.198,77.351 cw(c114.487,77.106) 115.239,77.106 cw(c114.487,77.106) 115.209,76.896 ; 115.198,77.361 ccw(c114.487,77.606) 115.211,77.404 ; 115.198,77.851 cw(c114.487,77.606) 115.239,77.606 cw(c114.487,77.606) 115.211,77.404 ; 115.198,77.861 ccw(c114.487,78.106) 115.213,77.912 ; 115.202,62.164 115.117,62.164 ; 115.202,70.374 ccw(c114.487,70.606) pad.@115.213,70.8 ; 115.367,65.298 cw(c115.751,66.202) 114.895,65.72 ; 115.377,65.294 115.377,65.212 ; 115.383,65.291 ccw(c115.751,66.202) 115.708,65.221 ; 115.537,78.42 115.377,78.42 ; 115.539,78.419 ccw(c115.937,79.056) 115.885,78.306 ; 115.68,70.362 cw(c115.937,69.656) 115.885,70.406 ; 115.682,70.367 ccw(c115.437,69.656) 115.377,70.405 ; 115.717,65.22 cw(c115.751,66.202) 115.708,65.221 ; 116.18,70.362 cw(c116.437,69.656) 116.393,70.406 ; 116.182,70.367 ccw(c115.937,69.656) 115.885,70.406 ; 116.335,78.419 cw(c115.937,79.056) 115.885,78.306 ; 116.338,78.42 116.393,78.42 ; 116.537,78.42 116.393,78.42 ; 116.539,78.419 ccw(c116.937,79.056) 116.898,78.305 ccw(c116.937,79.056) 116.901,78.305 ; 116.68,70.362 cw(c116.937,69.656) 116.898,70.407 cw(c116.937,69.656) 116.901,70.407 ; 116.682,70.367 ccw(c116.437,69.656) 116.393,70.406 ; 116.901,95.598 116.901,95.184 ; 117.182,70.367 ccw(c116.937,69.656) 116.901,70.407 ; 117.182,78.345 cw(c116.937,79.056) 116.901,78.305 ; 117.192,70.367 cw(c117.437,69.656) 117.409,70.407 ; 117.192,78.345 ccw(c117.437,79.056) 117.409,78.305 ; 117.398,70.407 cw(c117.437,69.656) 117.409,70.407 ; 117.411,70.407 ccw(c117.437,69.656) 117.409,70.407 ; 117.68,70.362 cw(c117.937,69.656) 117.911,70.407 cw(c117.937,69.656) 117.917,70.407 ; 117.682,70.367 ccw(c117.437,69.656) 117.409,70.407 ; 117.692,78.345 ccw(c117.937,79.056) 117.917,78.305 ; 117.694,78.35 cw(c117.437,79.056) 117.411,78.305 cw(c117.437,79.056) 117.409,78.305 ; 117.911,78.305 ccw(c117.937,79.056) 117.917,78.305 ; 117.916,93.856 cw(c119.314,93.954) 117.917,94.067 ; 117.917,93.841 117.917,93.66 ; 117.918,93.832 ccw(c119.314,93.954) 117.944,93.66 ; 117.924,78.305 cw(c117.937,79.056) 117.917,78.305 ; 118.18,70.362 cw(c118.437,69.656) 118.424,70.407 ; 118.182,70.367 ccw(c117.937,69.656) 117.917,70.407 ; 118.182,78.345 cw(c117.937,79.056) 117.917,78.305 ; 118.192,78.345 ccw(c118.437,79.056) 118.425,78.304 ; 118.413,95.028 cw(c119.314,93.954) 118.425,95.038 ; 118.432,95.043 ccw(c119.314,93.954) 118.425,95.038 ; 118.437,78.304 cw(c118.437,79.056) 118.425,78.304 ; 118.68,70.362 cw(c118.937,69.656) 118.933,70.408 ; 118.682,70.367 ccw(c118.437,69.656) 118.425,70.408 118.425,70.8 ; 118.835,78.419 cw(c118.437,79.056) 118.425,78.304 ; 118.838,78.42 118.933,78.42 ; 119.037,78.42 118.937,78.42 118.933,78.42 ; 119.039,78.419 ccw(c119.437,79.056) 119.441,78.304 ; 119.046,92.136 118.933,92.136 ; 119.18,70.362 cw(c119.437,69.656) 119.437,70.408 ; 119.182,70.367 ccw(c118.937,69.656) 118.933,70.408 ; 119.437,78.304 ccw(c119.437,79.056) 119.441,78.304 ; 119.441,70.408 119.441,70.8 ; 119.45,70.407 cw(c119.437,69.656) 119.838,70.292 ; 119.45,78.305 cw(c119.437,79.056) 119.441,78.304 ; 119.485,92.563 cw(c119.314,93.954) 119.471,92.561 ; 119.682,78.345 cw(c119.437,79.056) 119.441,78.304 ; 119.692,78.345 ccw(c119.937,79.056) 119.949,78.304 ; 119.94,70.215 ccw(c119.437,69.656) 119.937,70.217 ccw(c119.437,69.656) 119.838,70.292 ; 119.944,70.223 cw(c120.437,69.656) 119.949,70.228 ; 120.166,59.247 120.166,59.624 ; 120.17,59.247 cw(c120.121,57.846) 120.457,59.207 ; 120.192,78.345 ccw(c120.437,79.056) 120.457,78.305 ; 120.194,78.35 cw(c119.937,79.056) 119.949,78.304 ; 120.45,70.407 cw(c120.437,69.656) 120.457,70.407 ; 120.463,70.407 ccw(c120.437,69.656) 120.457,70.407 ; 120.68,70.362 cw(c120.937,69.656) 120.963,70.407 cw(c120.937,69.656) 120.965,70.407 ; 120.682,70.367 ccw(c120.437,69.656) 120.457,70.407 ; 120.692,78.345 ccw(c120.937,79.056) 120.965,78.305 ; 120.694,78.35 cw(c120.437,79.056) 120.463,78.305 cw(c120.437,79.056) 120.457,78.305 ; 120.707,93.797 120.767,93.858 ; 120.708,93.807 ccw(c119.314,93.954) 120.699,94.168 ; 120.768,93.858 120.965,94.055 ; 120.905,59.008 ccw(c120.121,57.846) 120.714,59.116 ; 120.907,59.007 120.907,59.116 ; 120.963,78.305 ccw(c120.937,79.056) 120.965,78.305 ; 120.976,78.305 cw(c120.937,79.056) 120.965,78.305 ; 121.182,70.367 ccw(c120.937,69.656) 120.965,70.407 ; 121.182,78.345 cw(c120.937,79.056) 120.965,78.305 ; 121.192,70.367 cw(c121.437,69.656) 121.473,70.407 ; 121.192,78.345 ccw(c121.437,79.056) 121.473,78.305 ; 121.463,70.407 cw(c121.437,69.656) 121.473,70.407 ; 121.476,70.407 ccw(c121.437,69.656) 121.473,70.407 ; 121.68,70.362 cw(c121.937,69.656) 121.976,70.407 cw(c121.937,69.656) 121.981,70.406 ; 121.682,70.367 ccw(c121.437,69.656) 121.473,70.407 ; 121.692,78.345 ccw(c121.937,79.056) 121.981,78.306 ; 121.694,78.35 cw(c121.437,79.056) 121.476,78.305 cw(c121.437,79.056) 121.473,78.305 ; 121.976,78.305 ccw(c121.937,79.056) 121.981,78.306 ; 121.989,78.306 cw(c121.937,79.056) 121.981,78.306 ; 122.18,70.362 cw(c122.437,69.656) 122.489,70.406 ; 122.182,70.367 ccw(c121.937,69.656) 121.981,70.406 ; 122.182,78.345 cw(c121.937,79.056) 121.981,78.306 ; 122.192,78.345 ccw(c122.437,79.056) 122.489,78.306 ; 122.374,61.067 ccw(c122.835,61.935) 122.489,61.015 ; 122.569,88.871 cw(c121.624,88.601) 122.571,88.864 ; 122.595,88.513 cw(c122.017,87.718) 122.934,88.072 ; 122.603,88.515 ccw(c121.624,88.601) 122.606,88.58 ; 122.68,70.362 cw(c122.937,69.656) 122.997,70.405 ; 122.682,70.367 ccw(c122.437,69.656) 122.489,70.406 ; 122.692,78.345 ccw(c122.937,79.056) 122.906,78.305 ; 122.694,78.35 cw(c122.437,79.056) 122.489,78.306 ; 122.784,60.953 cw(c122.835,61.935) 122.778,60.954 ; 122.804,89.088 122.997,89.088 ; 122.911,78.305 cw(c122.937,79.056) 122.906,78.305 ; 122.993,87.838 ccw(c122.017,87.718) 122.934,88.072 ; 122.997,87.834 122.997,88.072 ; 122.997,89.281 122.997,89.088 ; 123.001,87.833 cw(c122.601,86.935) 123.356,87.564 ; 123.161,77.801 ccw(c123.887,77.606) 123.163,77.404 ; 123.169,70.371 ccw(c122.937,69.656) 122.997,70.405 ; 123.176,70.361 cw(c123.887,70.606) 123.161,70.8 ; 123.176,70.851 ccw(c123.887,70.606) 123.161,70.8 ; 123.176,71.351 ccw(c123.887,71.106) 123.163,71.308 ; 123.176,71.851 ccw(c123.887,71.606) 123.165,71.816 ; 123.176,72.351 ccw(c123.887,72.106) 123.168,72.324 ; 123.176,72.851 ccw(c123.887,72.606) 123.17,72.832 ; 123.176,73.351 ccw(c123.887,73.106) 123.173,73.34 ; 123.176,73.851 ccw(c123.887,73.606) 123.175,73.848 ; 123.176,74.351 ccw(c123.887,74.106) 123.181,73.849 ; 123.176,74.851 ccw(c123.887,74.606) 123.178,74.356 ; 123.176,74.861 cw(c123.887,75.106) 123.175,74.864 ; 123.176,76.851 ccw(c123.887,76.606) 123.168,76.388 ; 123.176,77.351 ccw(c123.887,77.106) 123.165,76.896 ; 123.176,77.361 cw(c123.887,77.606) 123.163,77.404 ; 123.181,70.849 cw(c123.887,71.106) 123.163,71.308 ; 123.181,71.349 cw(c123.887,71.606) 123.165,71.816 ; 123.181,71.849 cw(c123.887,72.106) 123.168,72.324 ; 123.181,72.349 cw(c123.887,72.606) 123.17,72.832 ; 123.181,72.849 cw(c123.887,73.106) 123.173,73.34 ; 123.181,73.349 cw(c123.887,73.606) 123.175,73.848 ; 123.181,74.349 cw(c123.887,74.606) 123.178,74.356 ; 123.181,76.849 cw(c123.887,77.106) 123.165,76.896 ; 123.312,89.596 123.505,89.596 ; 123.32,75.599 cw(c123.887,75.106) 123.326,75.606 ; 123.328,75.609 ccw(c123.887,75.106) 123.326,75.606 ; 123.375,87.54 ccw(c122.601,86.935) 123.373,87.542 ; 123.5,75.962 ccw(c123.887,76.606) 123.505,75.959 ; 123.505,89.789 123.505,89.596 ; 123.511,75.955 cw(c123.887,76.606) 123.505,75.959 ; 123.652,69.888 cw(c122.937,69.656) 123.678,69.784 ; 123.655,69.891 ccw(c123.887,70.606) 123.887,69.854 124.013,69.854 ; 123.689,68.481 123.689,68.768 ; 123.722,64.959 123.977,64.704 ; 123.723,64.958 ccw(c123.911,65.923) 124.013,64.946 ; 123.82,90.104 124.013,90.104 ; 124.029,68.416 cw(c124.994,68.228) 124.17,68.764 cw(c124.994,68.228) 124.173,68.768 ; pad.@124.894,65.923 cw(c123.911,65.923) pad.@124.872,65.72 ; 124.929,88.134 ccw(c125.249,87.205) 124.922,88.132 ; 125.028,69.21 ccw(c124.994,68.228) 124.521,69.09 ; 125.258,57.713 125.029,57.713 ; 125.272,57.713 125.537,57.713 ; 125.534,90.198 125.029,90.198 ; 125.722,67.569 125.722,67.244 ; 125.724,67.571 ccw(c124.994,68.228) 125.853,67.752 ; 126.269,69.877 cw(c126.087,70.606) 126.087,69.854 126.045,69.854 ; 126.269,75.835 ccw(c126.087,75.106) 126.139,75.856 ccw(c126.087,76.606) 126.269,75.877 ; 126.272,69.877 126.553,69.877 ; 126.272,75.877 126.358,75.877 126.372,75.877 ; 126.553,65.631 126.553,65.72 ; 126.642,65.72 126.553,65.72 ; pad.@127.168,66.246 pad.@127.15,66.228 ; pad.@127.17,66.248 127.184,66.262 127.569,66.647 ; 128.157,67.74 cw(c129.41,67.234) 128.161,67.752 ; 128.166,67.762 ccw(c129.41,67.234) 128.161,67.752 ; 129.083,68.545 ccw(c129.41,67.234) 128.585,68.305 ; 129.093,68.548 129.093,68.768 ; 129.106,68.551 cw(c129.41,67.234) 129.601,68.572 ; 129.582,87.469 129.601,87.469 129.682,87.469 129.682,87.738 ; 130.073,89.765 cw(c129.091,89.799) 130.073,89.756 ; 130.204,68.327 ccw(c129.41,67.234) 130.2,68.33 ; 131.593,68.895 131.125,68.895 ; 134.365,81.468 134.681,81.468 ; 135.731,77.283 C56.2@135.697,77.283 ; 135.738,77.286 cw(c136.214,76.427) 136.109,77.404 ; 137.111,84.505 ccw(c138.451,84.095) 137.182,83.5 ; 137.114,84.516 136.986,84.516 ; 137.118,84.528 cw(c138.451,84.095) 137.221,84.767 ; 137.393,85.015 cw(c138.451,84.095) 137.402,85.024 ; 137.409,85.033 ccw(c138.451,84.095) 137.402,85.024 ; 137.588,82.991 cw(c138.451,84.095) 137.584,82.993 ; 137.972,85.412 ccw(c138.451,84.095) 137.729,85.296 ; 138.029,85.564 cw(c138.999,85.717) 138.028,85.568 ; 138.408,86.502 ccw(c138.999,85.717) pad.@138.237,86.338 ; 138.408,86.503 cw(c139.634,87.183) 138.385,86.548 ; 138.515,88.027 ccw(c139.634,87.183) 138.285,87.564 ; 138.518,88.031 138.477,88.072 ; 138.839,53.306 139.253,53.306 ; 139.213,63.901 ccw(c138.804,64.704) 139.549,64.196 ; 139.22,63.894 139.332,63.782 139.761,63.782 ; 139.442,65.336 ccw(c138.804,65.974) 139.444,65.339 ; 139.442,65.342 cw(c138.804,64.704) 139.444,65.339 ; 139.442,66.606 ccw(c138.804,67.244) 139.444,66.609 ; 139.442,66.612 cw(c138.804,65.974) 139.444,66.609 ; 139.442,67.876 ccw(c138.804,68.514) 139.444,67.879 ; 139.442,67.882 cw(c138.804,67.244) 139.444,67.879 ; 139.605,68.928 139.761,68.928 ; 139.607,68.923 cw(c138.804,68.514) 139.669,68.768 ; 139.666,65.71 cw(c138.804,65.974) 139.444,65.339 ; 139.669,65.72 139.761,65.72 ; 139.671,65.725 ccw(c138.804,65.974) 139.706,65.974 ccw(c138.804,65.974) 139.671,66.223 ccw(c138.804,65.974) 139.669,66.228 ; 139.89,61.572 ccw(c141.072,60.917) 139.884,61.562 ; 139.979,59.823 cw(c141.072,60.617) 139.976,59.825 ; 140.16,53.292 140.505,53.292 ; 140.16,55.796 140.16,55.56 ; 140.175,55.796 140.175,56.068 ; 140.191,56.937 140.044,57.084 ; 140.505,53.306 140.16,53.306 ; 141.33,59.29 ccw(c141.072,60.617) 141.335,59.291 ; 141.337,73.116 pad.@141.793,73.116 ; 141.343,73.126 ccw(c140.142,73.848) 141.451,73.346 ; 142.137,65.725 ccw(c143.004,65.974) 142.139,65.72 ; 142.137,66.223 ccw(c143.004,65.974) 142.139,65.72 ; 142.139,66.228 141.793,66.228 ; 142.142,65.71 cw(c143.004,65.974) 142.139,65.72 ; 142.142,66.238 cw(c143.004,65.974) 142.301,66.538 ; 142.201,61.66 142.422,61.881 pad.@142.809,61.881 ; 142.204,61.656 142.301,61.656 ; 142.206,61.653 cw(c141.072,60.917) 142.301,61.479 ; 142.301,61.761 142.301,61.656 ; 142.355,65.348 cw(c143.004,65.974) 142.301,65.409 ; 142.366,65.342 ccw(c143.004,64.704) 142.301,65.269 ; 142.366,66.606 cw(c143.004,67.244) 142.364,66.609 ; 142.366,66.612 ccw(c143.004,65.974) 142.364,66.609 ; 142.954,58.991 142.809,58.991 ; 142.954,59.021 143.317,59.021 ; 144.344,84.339 ccw(c144.396,85.32) 144.351,84.338 ; pad.@145.325,85 cw(c144.396,85.32) 144.961,84.516 ; pad.@145.327,85.006 pad.@145.349,85.006 ; pad.@145.61,73.848 pad.@145.349,73.848 ; 168.328,113.983 cw(c167.955,113.218) 168.335,113.98 ; 168.558,113.819 168.717,113.66 ; 170.731,110.442 170.731,110.424 ; 170.731,110.456 170.731,110.932 ; 171.082,108.631 170.813,108.9 ; 171.086,108.574 cw(c171.467,107.757) 171.257,108.634 ; 173.643,101.18 173.797,101.026 ; 173.676,101.213 173.797,101.213 ; 176.845,99.676 176.845,99.756 ; 176.925,99.756 176.845,99.756 ; 177.135,103.046 177.135,102.804 ; 177.154,107.388 176.939,107.603 IC5.4@176.939,107.884 ; 177.167,103.045 177.353,103.045 ; 177.167,107.389 177.353,107.389 ; 177.353,100.184 177.353,100.264 ; 177.433,100.264 177.353,100.264 ; 177.666,111.051 177.666,109.408 ; 177.698,111.051 177.698,109.422 177.861,109.422 ; 177.704,114.996 R135.2@177.861,114.996 ; R135.2@177.861,114.839 R135.2@177.861,114.996 ; R135.2@178.19,114.51 177.539,115.162 177.539,115.504 ; 178.369,114.308 R135.2@178.369,114.488 ; 178.946,107.344 ccw(c178.667,106.487) 178.877,107.364 ; 178.951,107.343 179.385,107.343 ; pad.@179.53,108.156 pad.@179.53,107.884 ; pad.@179.53,108.17 pad.@179.53,108.392 ; 181.163,113.585 180.909,113.585 ; 181.242,113.585 180.909,113.917 ; 183.063,103.784 183.181,103.784 183.181,103.312 ; 183.063,103.82 183.181,103.82 ; 183.063,103.856 183.181,103.856 ; 183.246,103.784 183.246,103.82 ; 183.449,100.044 183.449,100.264 ; 183.687,99.806 183.414,100.079 ; 183.696,99.803 cw(c183.356,98.756) 183.817,99.756 ; 183.839,99.746 ccw(c183.356,98.756) 183.832,99.749 ; 184.786,108.9 C9.1@184.973,108.9 ; 184.939,108.747 184.88,108.807 184.465,109.221 ; 184.954,108.747 184.973,108.747 ; 185.192,99.683 ccw(c184.815,98.647) 184.973,99.738 ; 185.2,99.68 185.481,99.68 ; 185.448,102.133 184.973,102.133 ; 185.778,101.788 D7.1@185.481,101.788 ; pad.@185.989,97.326 pad.@185.989,97.216 ; 185.989,101.577 185.989,101.28 ; 186.195,108.631 186.258,108.631 186.497,108.631 ; 186.421,97.757 186.061,97.398 185.898,97.234 pad.@185.898,97.216 ; 186.454,97.757 186.454,97.529 186.497,97.529 ; 186.454,99.532 186.454,99.248 ; 186.473,99.424 186.473,99.756 ; 189.277,102.628 189.277,102.296 ; 189.293,102.318 189.545,102.318 ; C14.1@189.386,97.614 C14.1@189.037,97.614 ; 190.359,99.839 cw(c190.905,99.484) 190.361,99.843 ; 190.494,97.378 190.053,97.378 ; 190.495,97.378 ccw(c190.905,97.884) 190.561,97.331 ; 191.371,100.13 cw(c192.336,99.942) 191.372,100.136 ; 191.753,102.291 192.085,102.291 ; 191.753,102.296 191.577,102.296 ; 192.093,102.318 191.577,102.318 ; 192.151,97.303 cw(c191.855,97.884) 192.085,97.274 ; 192.155,97.305 192.25,97.305 192.593,97.305 ; C16.1@192.797,100.81 ccw(c192.336,99.942) C16.1@192.593,100.89 ; C16.1@192.799,100.808 C16.1@192.799,101.28 ; 194.203,97.234 ccw(c194.855,97.234) 194.204,97.216 ; 194.203,97.305 194.117,97.305 ; 194.472,96.707 cw(c194.855,97.234) 194.47,96.708 ; 194.803,102.007 194.803,102.205 194.625,102.205 ; 194.803,102.007 cw(c194.752,101.026) 195.133,101.932 ; 194.957,102.563 cw(c195.851,102.677) 194.956,102.567 cw(c195.851,102.677) 194.956,102.787 ; 194.957,102.791 194.957,103.182 ; 194.958,102.802 cw(c195.851,102.677) 195.07,103.128 ; 195.273,100.193 ccw(c194.752,101.026) 195.372,100.264 ; 195.33,100.19 cw(c195.33,99.334) 195.623,100.138 ; 195.629,100.136 195.641,100.136 ; 196.039,100.092 ccw(c195.805,99.484) 196.033,100.094 ; 197.554,101.799 cw(c197.351,102.677) 197.351,101.775 197.165,101.775 ; 197.56,101.8 C111.1@197.56,101.28 ; 198.071,103.404 ccw(c197.351,103.947) 198.072,103.406 ; 198.187,104.285 cw(c197.351,103.947) 198.253,103.947 cw(c197.351,103.947) 198.244,103.82 ; 199.197,97.379 199.197,97.216 ; 199.564,101.744 199.564,101.788 ; 199.568,101.745 cw(c199.705,100.772) 199.654,101.753 ; 199.654,101.788 199.564,101.788 ; 199.654,101.824 199.705,101.824 ; 199.883,104.435 cw(c199.188,105.13) 199.757,104.328 ; 199.895,104.447 cw(c199.188,105.13) 199.884,104.436 ; 199.942,104.494 199.884,104.436 ; 199.942,108.402 199.814,108.53 199.814,108.631 200.213,108.631 ; 200.831,103.404 cw(c201.551,103.947) 200.83,103.406 ; 201.02,101.948 200.721,101.948 ; 201.021,101.948 ccw(c201.551,102.677) 201.26,101.824 ; 202.275,100.172 202.753,100.172 ; 202.677,100.173 202.245,100.173 ; 203.345,104.799 ccw(c203.051,103.947) 203.261,104.824 ; 203.345,105.635 cw(c203.051,106.487) 203.261,105.61 ; 203.345,107.339 ccw(c203.051,106.487) 203.261,107.364 ; 203.347,104.799 203.769,104.799 ; 203.347,105.635 203.769,105.635 ; 203.347,107.339 203.769,107.339 ; 203.847,103.1 cw(c203.051,102.677) 203.85,103.095 ; 205.156,97.724 205.078,97.724 ; 205.293,97.861 205.293,98.232 ; 206.545,106.632 206.545,106.868 ; 206.595,104.346 206.595,104.836 ; 206.595,106.85 206.595,106.36 ; 206.658,102.06 206.309,102.06 ; 206.672,102.06 206.817,102.06 ; 206.672,104.564 206.817,104.564 ; 212.168,98.459 212.405,98.696 ; 212.962,99.923 212.962,99.756 ; 212.962,101.888 212.962,102.146 213.421,102.146 ; 213.421,108.631 213.421,108.392 ; 213.929,108.631 213.929,108.392 ; 214.437,108.631 214.437,108.392 ; 217.998,99.551 217.998,99.756 ; 217.998,100.903 217.998,99.248 ; 220.009,106.115 220.025,106.1 ; 220.058,96.865 cw(c220.519,95.997) 220.064,96.868 ; 220.305,97.108 220.064,96.868 ; 220.545,97.421 ccw(c221.377,98.486) 220.915,97.216 ; 220.668,102.804 220.533,102.804 ; 220.996,96.856 ccw(c220.519,95.997) 220.533,96.98 ; 221.003,96.853 221.041,96.853 ; 221.213,97.144 cw(c221.377,98.486) 221.041,97.177 ; 221.218,97.144 ccw(c221.422,98.105) 221.542,97.13 ccw(c221.422,98.105) 221.549,97.131 ; 221.837,97.214 cw(c221.422,98.105) 221.549,97.131 ; 221.84,97.216 ccw(c221.377,98.486) 221.843,97.217 ; 222.729,99.551 222.729,99.248 ; 222.802,99.551 222.802,99.756 ; 223.012,101.325 222.967,101.28 ; 223.309,106.489 223.309,106.868 ; 20.762,28.128 20.889,28.128 ; 20.762,28.128 20.762,27.874 20.889,27.747 ; 20.762,28.128 20.762,28.636 ; 20.762,28.636 20.762,29.144 ; 20.762,28.636 20.889,28.636 ; 20.762,29.144 20.762,29.652 ; 20.762,29.144 20.889,29.144 ; 20.762,29.652 20.762,30.16 ; 20.762,29.652 20.889,29.652 ; 20.762,30.16 20.889,30.16 ; 20.762,30.16 20.762,30.668 ; 20.762,30.668 20.889,30.668 ; 20.762,30.668 20.762,31.176 ; 20.762,31.176 20.762,31.684 ; 20.762,31.176 20.889,31.176 ; 20.762,31.684 20.889,31.684 ; 20.762,31.684 20.762,32.192 ; 20.762,32.192 20.889,32.192 ; 20.762,32.192 20.762,32.7 ; 20.762,32.7 20.889,32.7 ; 20.762,32.7 20.762,33.208 ; 20.762,33.208 20.762,33.716 ; 20.762,33.208 20.889,33.208 ; 20.762,33.716 20.889,33.716 ; 20.762,33.716 20.762,34.224 ; 20.762,34.224 pad.@20.762,34.732 ; 20.762,34.224 20.889,34.224 ; pad.@20.762,34.732 pad.@20.889,34.732 ; pad.@20.762,34.732 20.762,35.24 ; 20.762,35.24 20.889,35.24 ; 20.762,35.24 20.762,35.748 ; 20.762,35.748 20.889,35.748 ; 20.762,35.748 20.762,36.256 ; 20.762,36.256 20.889,36.256 ; 20.762,36.256 20.762,36.764 ; 20.762,36.764 20.889,36.764 ; 20.762,36.764 20.762,37.272 ; 20.762,37.272 20.889,37.272 ; 20.762,37.272 20.762,37.78 ; 20.762,37.78 20.889,37.78 ; 20.762,37.78 20.762,38.288 ; 20.762,38.288 20.889,38.288 ; 20.762,38.288 pad.@20.762,38.796 ; pad.@20.762,38.796 pad.@20.889,38.796 ; pad.@20.762,38.796 20.762,39.304 ; 20.762,39.304 20.889,39.304 ; 20.762,39.304 20.762,39.812 ; 20.762,39.812 20.889,39.812 ; 20.762,39.812 20.762,40.32 ; 20.762,40.32 20.889,40.32 ; 20.762,40.32 20.762,40.828 ; 20.762,40.828 20.889,40.828 ; 20.762,40.828 20.762,41.336 ; 20.762,41.336 20.889,41.336 ; 20.762,41.336 20.762,41.844 ; 20.762,41.844 20.762,42.352 ; 20.762,41.844 20.889,41.844 ; 20.762,42.352 20.762,42.86 ; 20.762,42.352 20.889,42.352 ; 20.762,42.86 20.762,43.368 ; 20.762,42.86 20.889,42.86 ; 20.762,43.368 20.762,43.876 ; 20.762,43.368 20.889,43.368 ; 20.762,43.876 20.889,43.876 ; 20.762,43.876 20.762,44.384 ; 20.762,44.384 20.889,44.384 ; 20.762,44.384 pad.@20.762,44.892 ; pad.@20.762,44.892 20.762,45.4 ; pad.@20.762,44.892 pad.@20.889,44.892 ; 20.762,45.4 20.889,45.4 ; 20.762,45.4 20.762,45.908 ; 20.762,45.908 20.762,46.416 ; 20.762,45.908 20.889,45.908 ; 20.762,46.416 20.762,46.924 ; 20.762,46.416 20.889,46.416 ; 20.762,46.924 20.762,47.432 ; 20.762,46.924 20.889,46.924 ; 20.762,47.432 20.762,47.94 ; 20.762,47.432 20.889,47.432 ; 20.762,47.94 20.889,47.94 ; 20.762,47.94 20.762,48.448 ; 20.762,48.448 20.762,48.956 ; 20.762,48.448 20.889,48.448 ; 20.762,48.956 20.762,49.464 ; 20.762,48.956 20.889,48.956 ; 20.762,49.464 20.889,49.464 ; 20.762,49.464 20.762,49.972 ; 20.762,49.972 20.762,50.48 ; 20.762,49.972 20.889,49.972 ; 20.762,50.48 pad.@20.889,50.48 ; 20.762,50.48 20.762,50.988 ; 20.762,50.988 20.762,51.496 ; 20.762,50.988 pad.@20.889,50.988 ; 20.762,51.496 20.762,52.004 ; 20.762,51.496 20.889,51.496 ; 20.762,52.004 20.889,52.004 ; 20.762,52.004 20.762,52.512 ; 20.762,52.512 20.762,53.02 ; 20.762,52.512 20.889,52.512 ; 20.762,53.02 20.762,53.528 ; 20.762,53.02 20.889,53.02 ; 20.762,53.528 20.889,53.528 ; 20.762,53.528 20.762,54.036 ; 20.762,54.036 20.762,54.544 ; 20.762,54.036 20.889,54.036 ; 20.762,54.544 20.762,55.052 ; 20.762,54.544 20.889,54.544 ; 20.762,55.052 20.889,55.052 ; 20.762,55.052 20.762,55.179 20.889,55.369 ; 20.889,27.747 21.016,27.62 ; 20.889,27.747 20.889,28.128 ; 20.889,28.128 20.889,28.636 ; 20.889,28.128 21.397,28.128 ; 20.889,28.636 20.889,29.144 ; 20.889,28.636 21.397,28.636 ; 20.889,29.144 21.397,29.144 ; 20.889,29.144 20.889,29.652 ; 20.889,29.652 21.397,29.652 ; 20.889,29.652 20.889,30.16 ; 20.889,30.16 20.889,30.668 ; 20.889,30.16 21.397,30.16 ; 20.889,30.668 20.889,31.176 ; 20.889,30.668 21.397,30.668 ; 20.889,31.176 20.889,31.684 ; 20.889,31.176 21.397,31.176 ; 20.889,31.684 21.397,31.684 ; 20.889,31.684 20.889,32.192 ; 20.889,32.192 20.889,32.7 ; 20.889,32.192 21.397,32.192 ; 20.889,32.7 20.889,33.208 ; 20.889,32.7 21.397,32.7 ; 20.889,33.208 20.889,33.716 ; 20.889,33.208 21.397,33.208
